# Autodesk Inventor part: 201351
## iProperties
Created: 2007-11
Part Number: 201351
Material: Stainless Steel
Document SubType Name: Modeling
Designer: JJ
Density: 8.08 g/cm^3
Mass: 101.36 g
Surface Area: 47.5454 cm^2
Volume: 12.5446 cm^3
Description: BALL SCREW SHAFT
CustomPartVersion: 1
Component Category: Lower Component
Author: JJ
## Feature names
1. Revolution1
2. Chamfer4
3. Chamfer1
4. Chamfer2
5. Chamfer3
6. Extrusion1
7. Revolution2
